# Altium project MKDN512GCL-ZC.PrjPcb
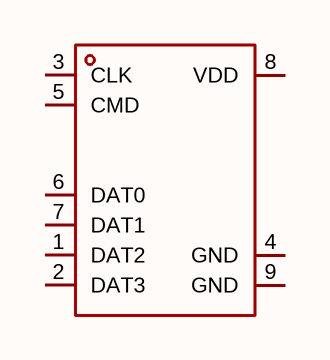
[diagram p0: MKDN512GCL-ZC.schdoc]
1 sheet, 1 parts. Net scope: global (net labels, ports and power ports of the same name join across sheets).

## Sheet MKDN512GCL-ZC.schdoc
size 127 x 101 mm

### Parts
U?  mkdn512gcl-zc  [LGA-16_L12.5-W9.0-P1.27-TL-EP]  (value not drawn)

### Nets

Not connected (* = marked no-connect by the designer): U? 1(DAT2) 2(DAT3) 3(CLK) 4(GND) 5(CMD) 6(DAT0) 7(DAT1) 8(VDD) 9(GND)

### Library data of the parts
U? = mkdn512gcl-zc: 存储容量:512Gbit;时钟频率(fc):208MHz;工作电压:2.7V~3.6V;; Manufacturer: MK(米客方德); AddInBom: yes; ModelId: aae4acadbbb4480ebd429fe2f08c27d7; ModelTransform: 492.125,354.33,0,0,0,0,0,0,0; Interface: SD接口; Clock Frequency: 208MHz; Standby Supply Current: 90uA; ECC: 有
